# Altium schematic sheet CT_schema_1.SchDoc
size 785 x 593 mm
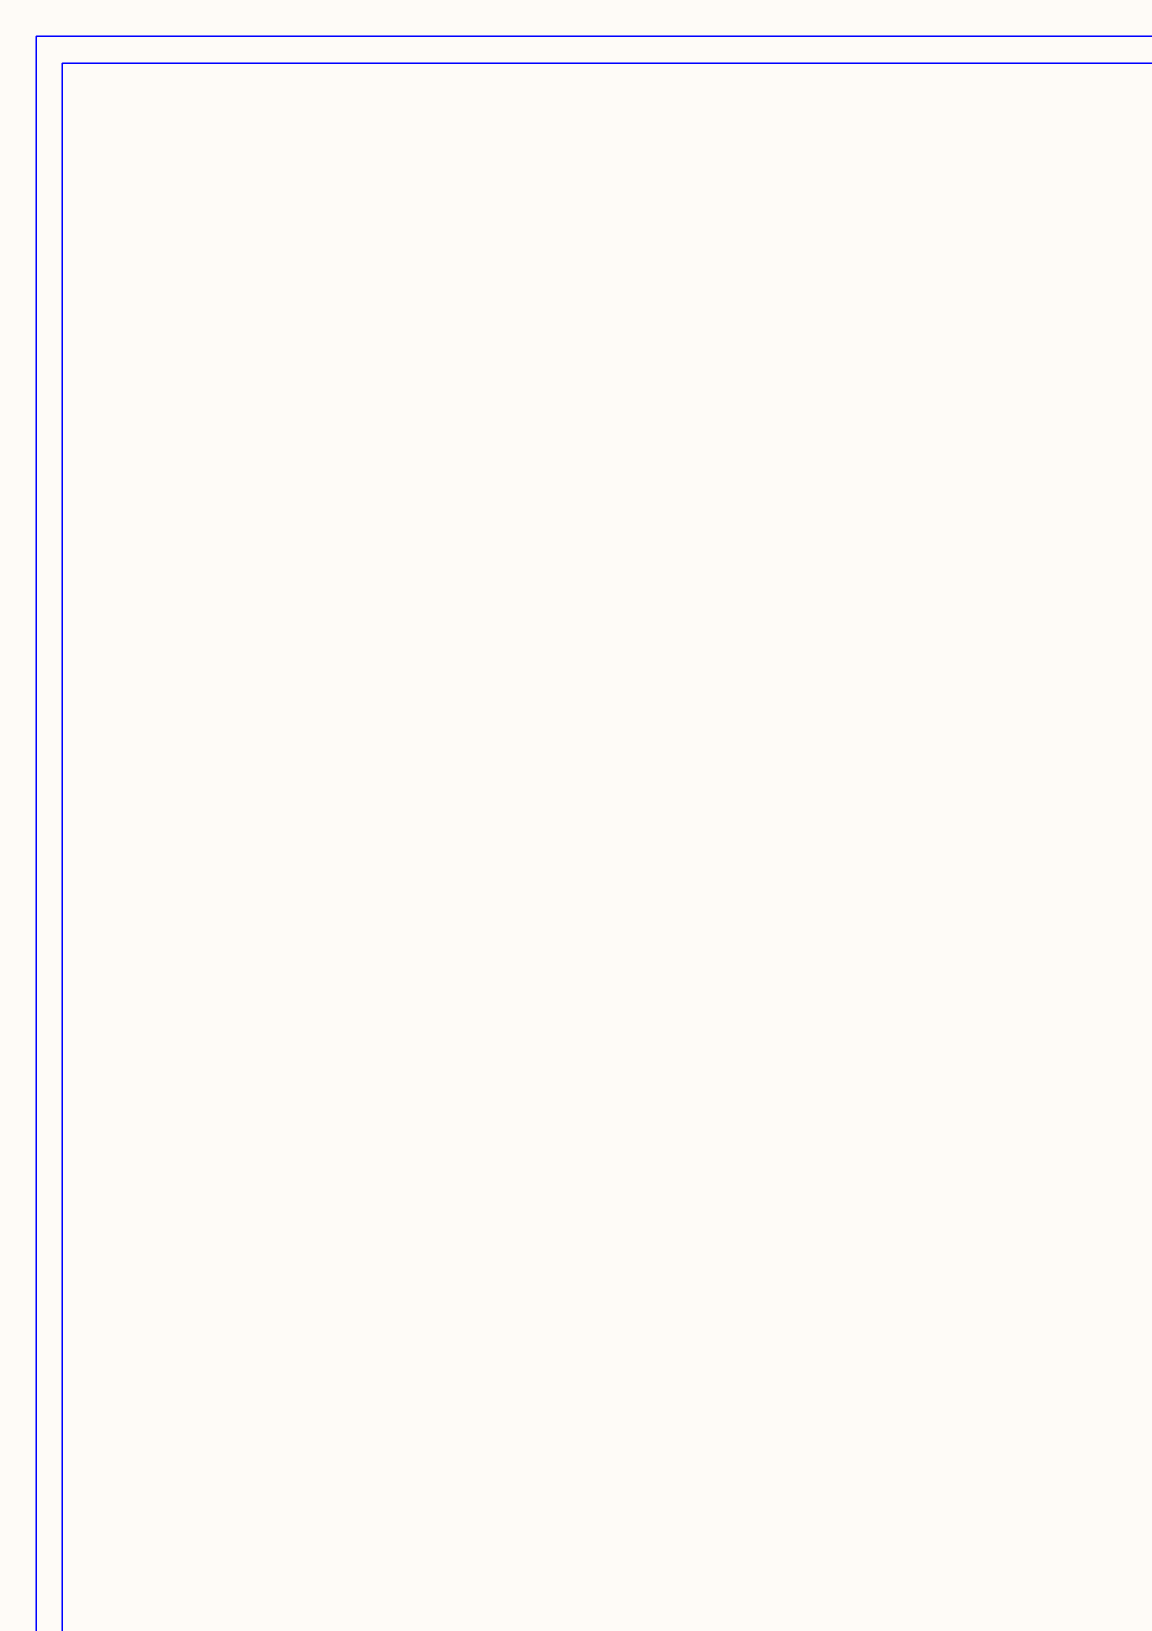
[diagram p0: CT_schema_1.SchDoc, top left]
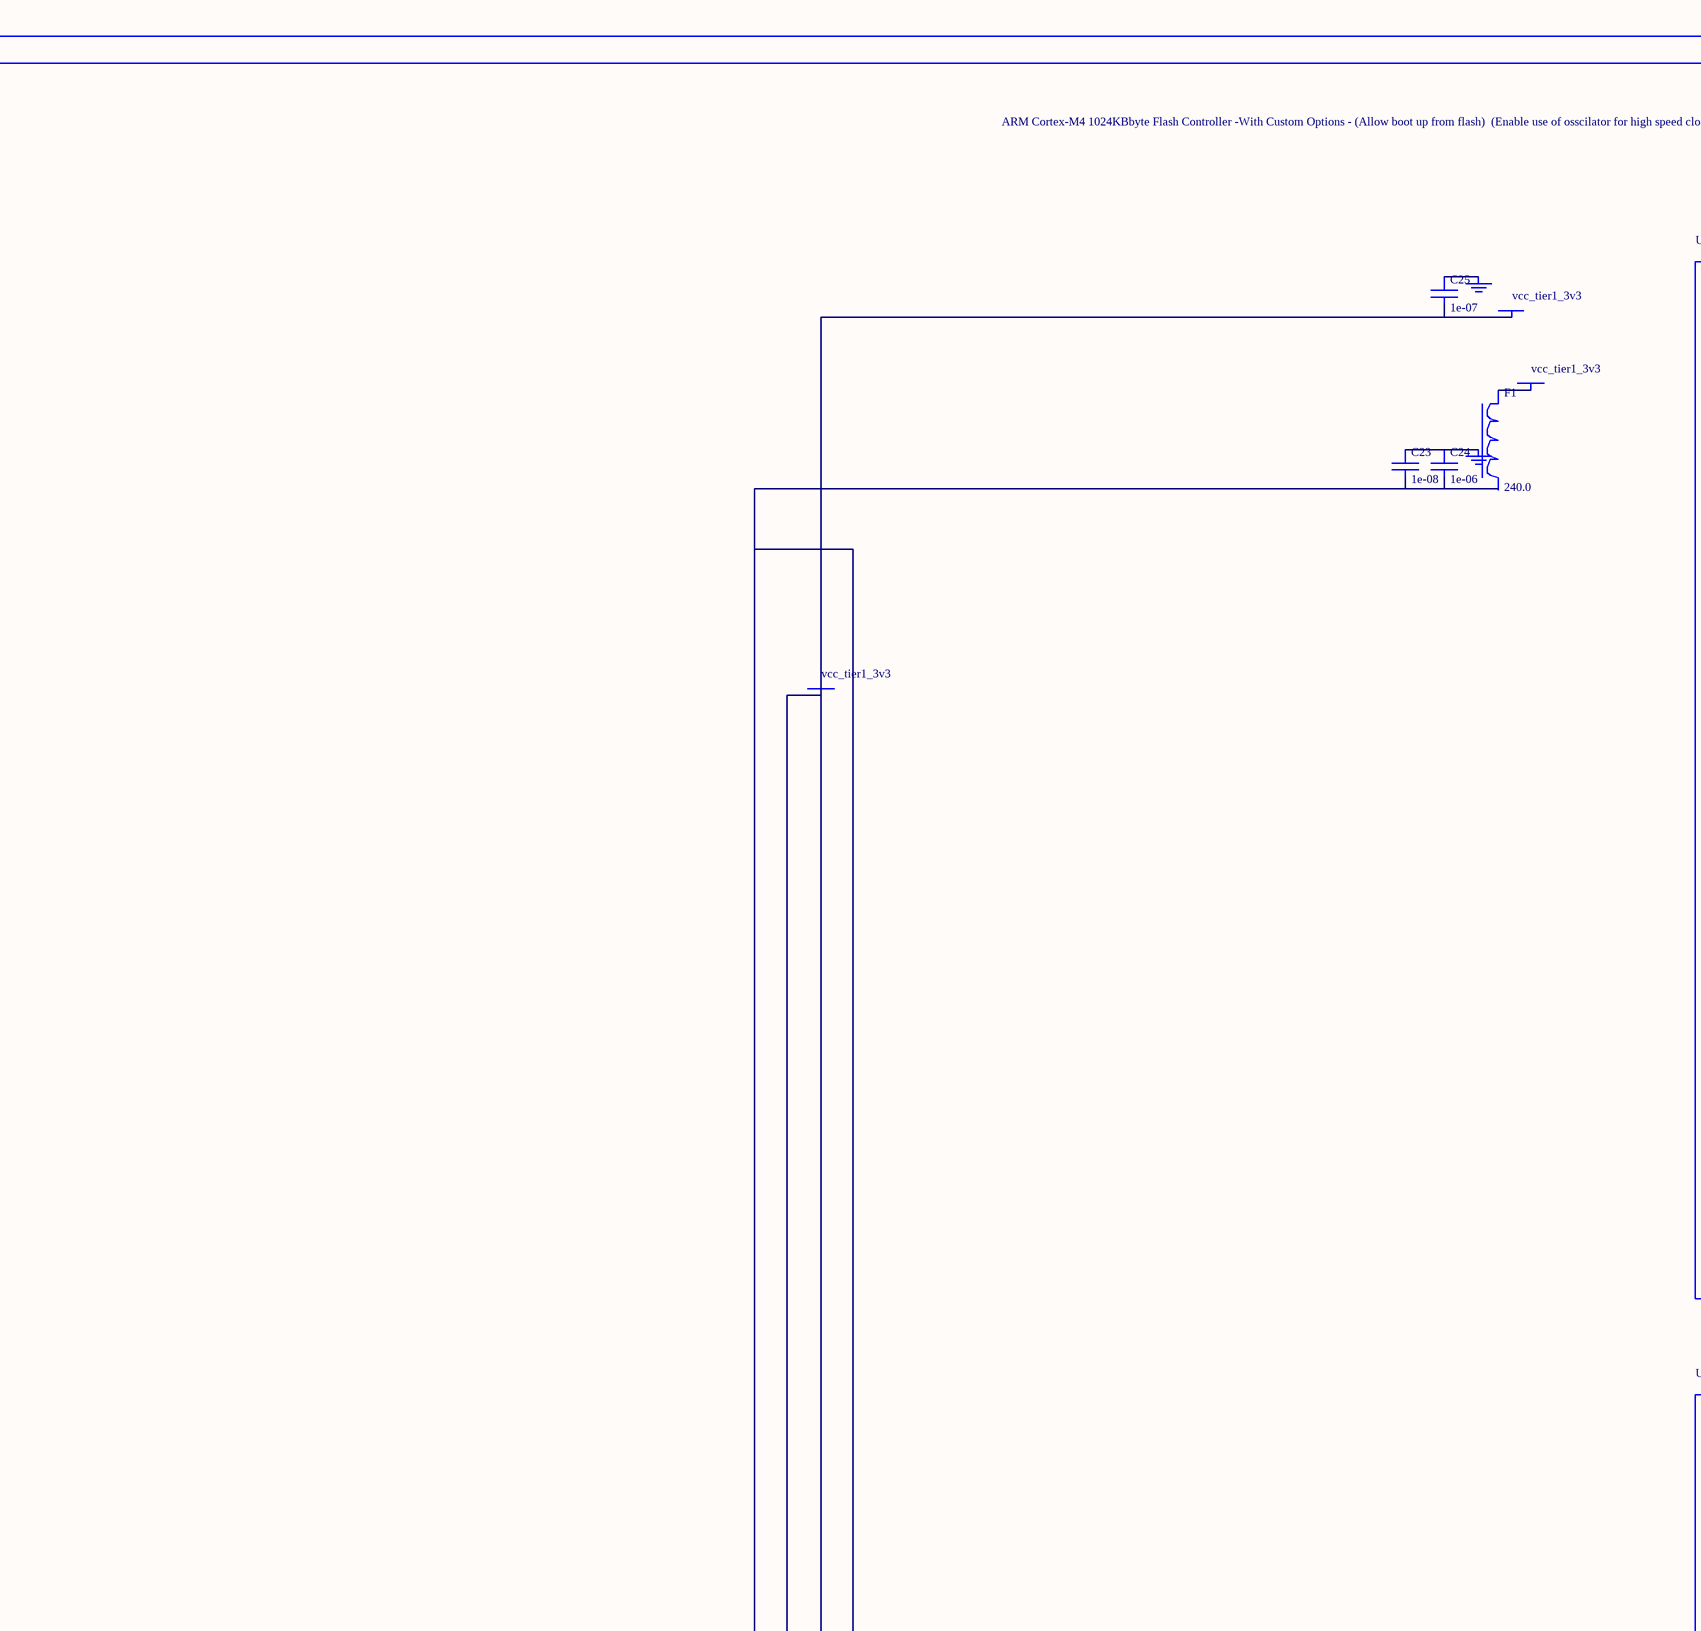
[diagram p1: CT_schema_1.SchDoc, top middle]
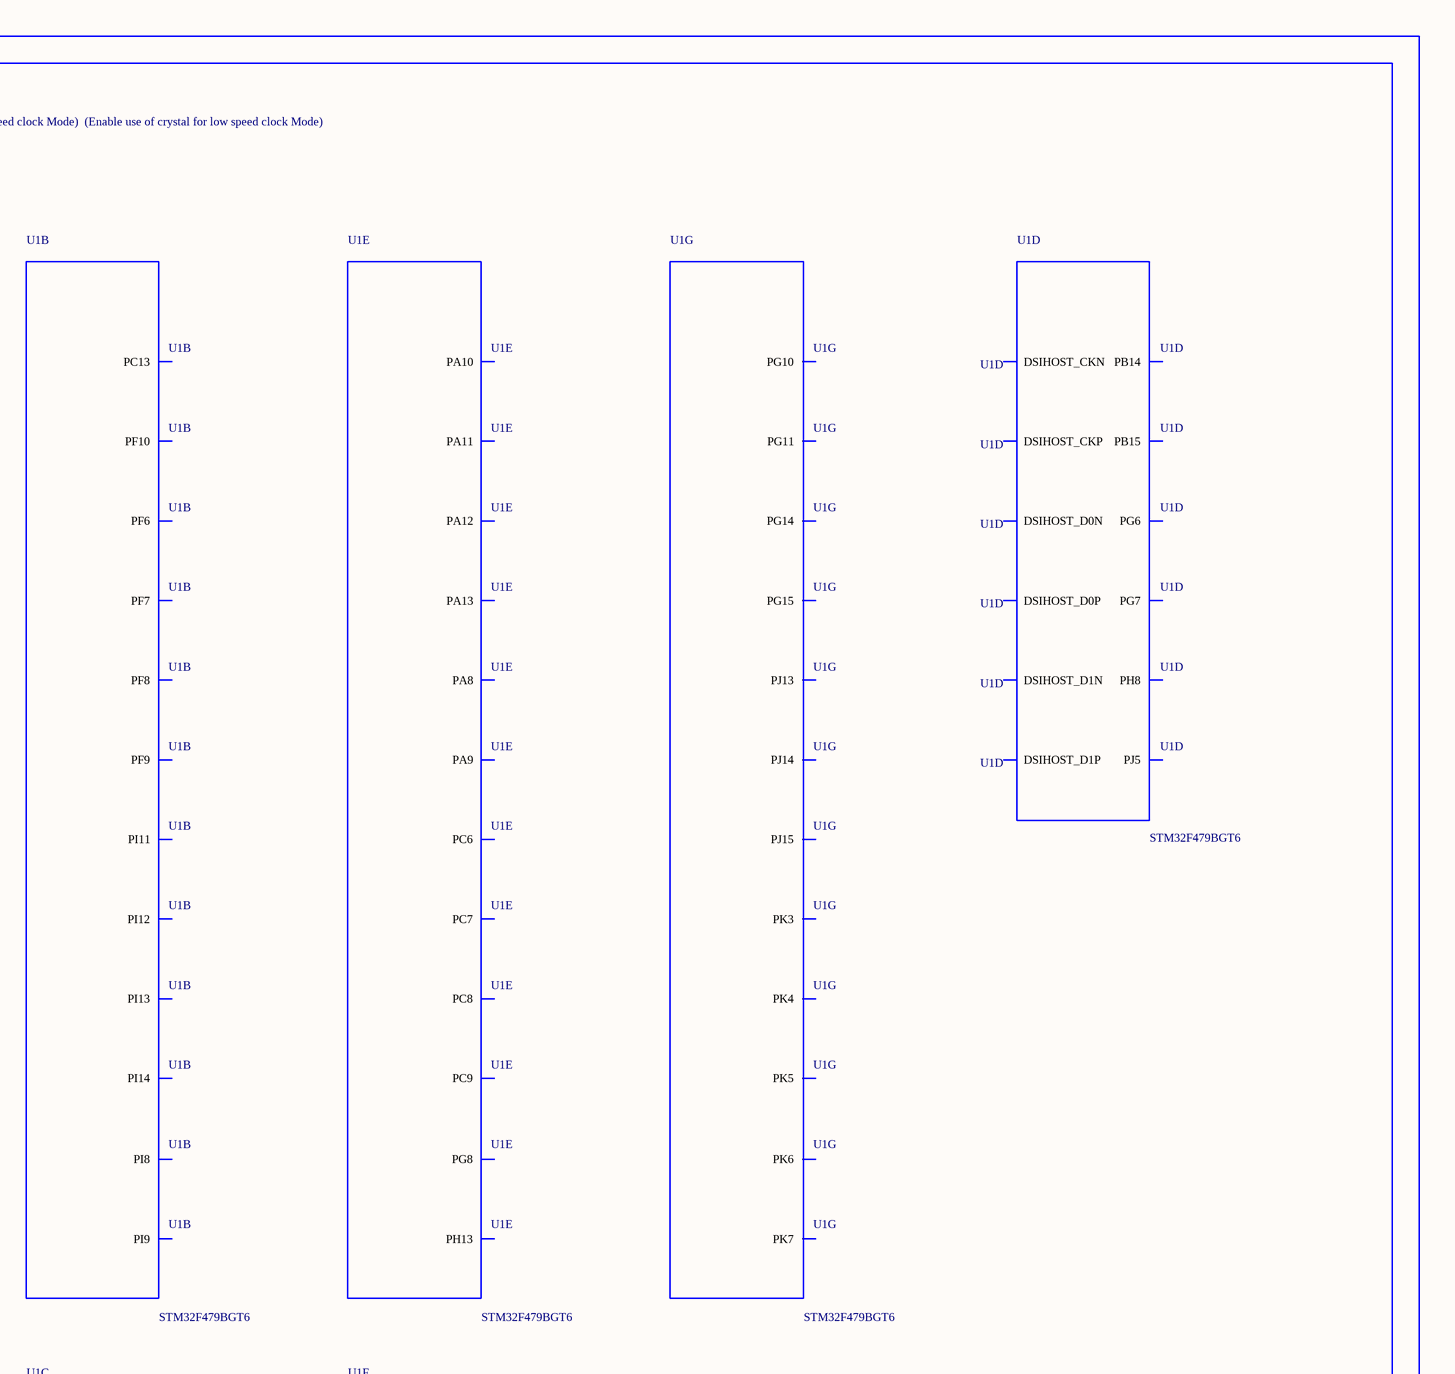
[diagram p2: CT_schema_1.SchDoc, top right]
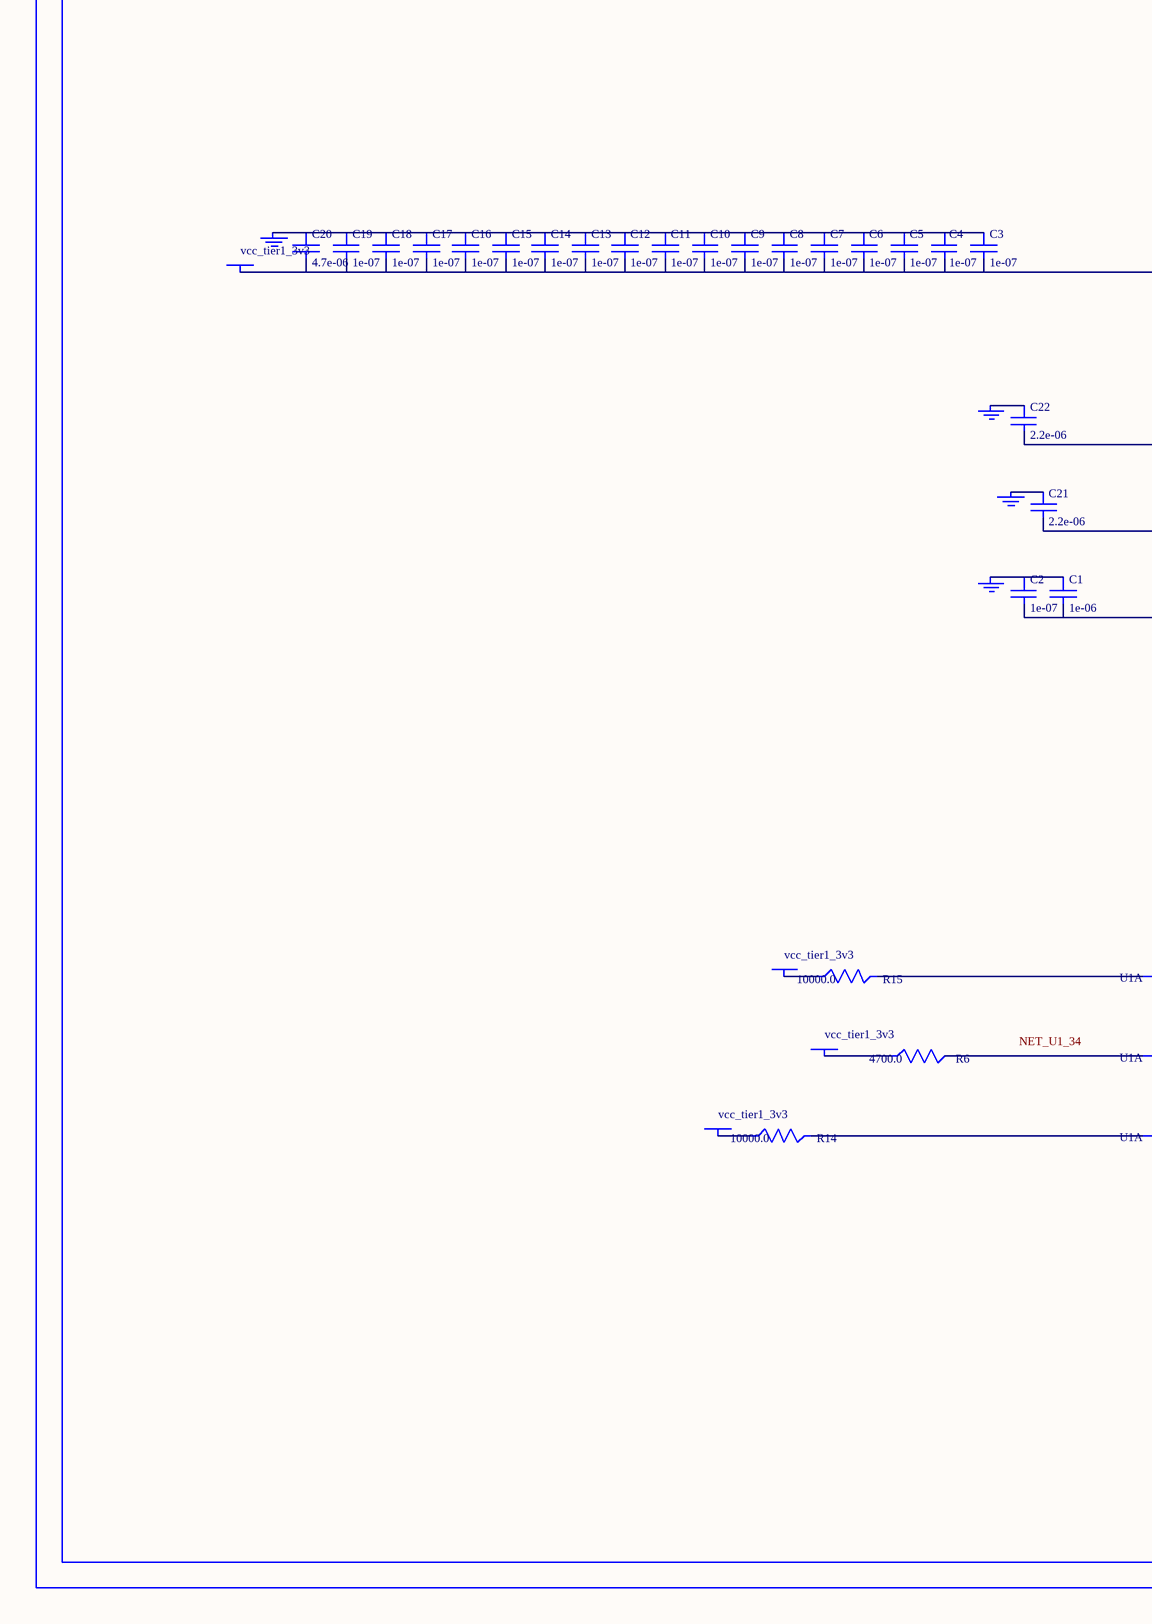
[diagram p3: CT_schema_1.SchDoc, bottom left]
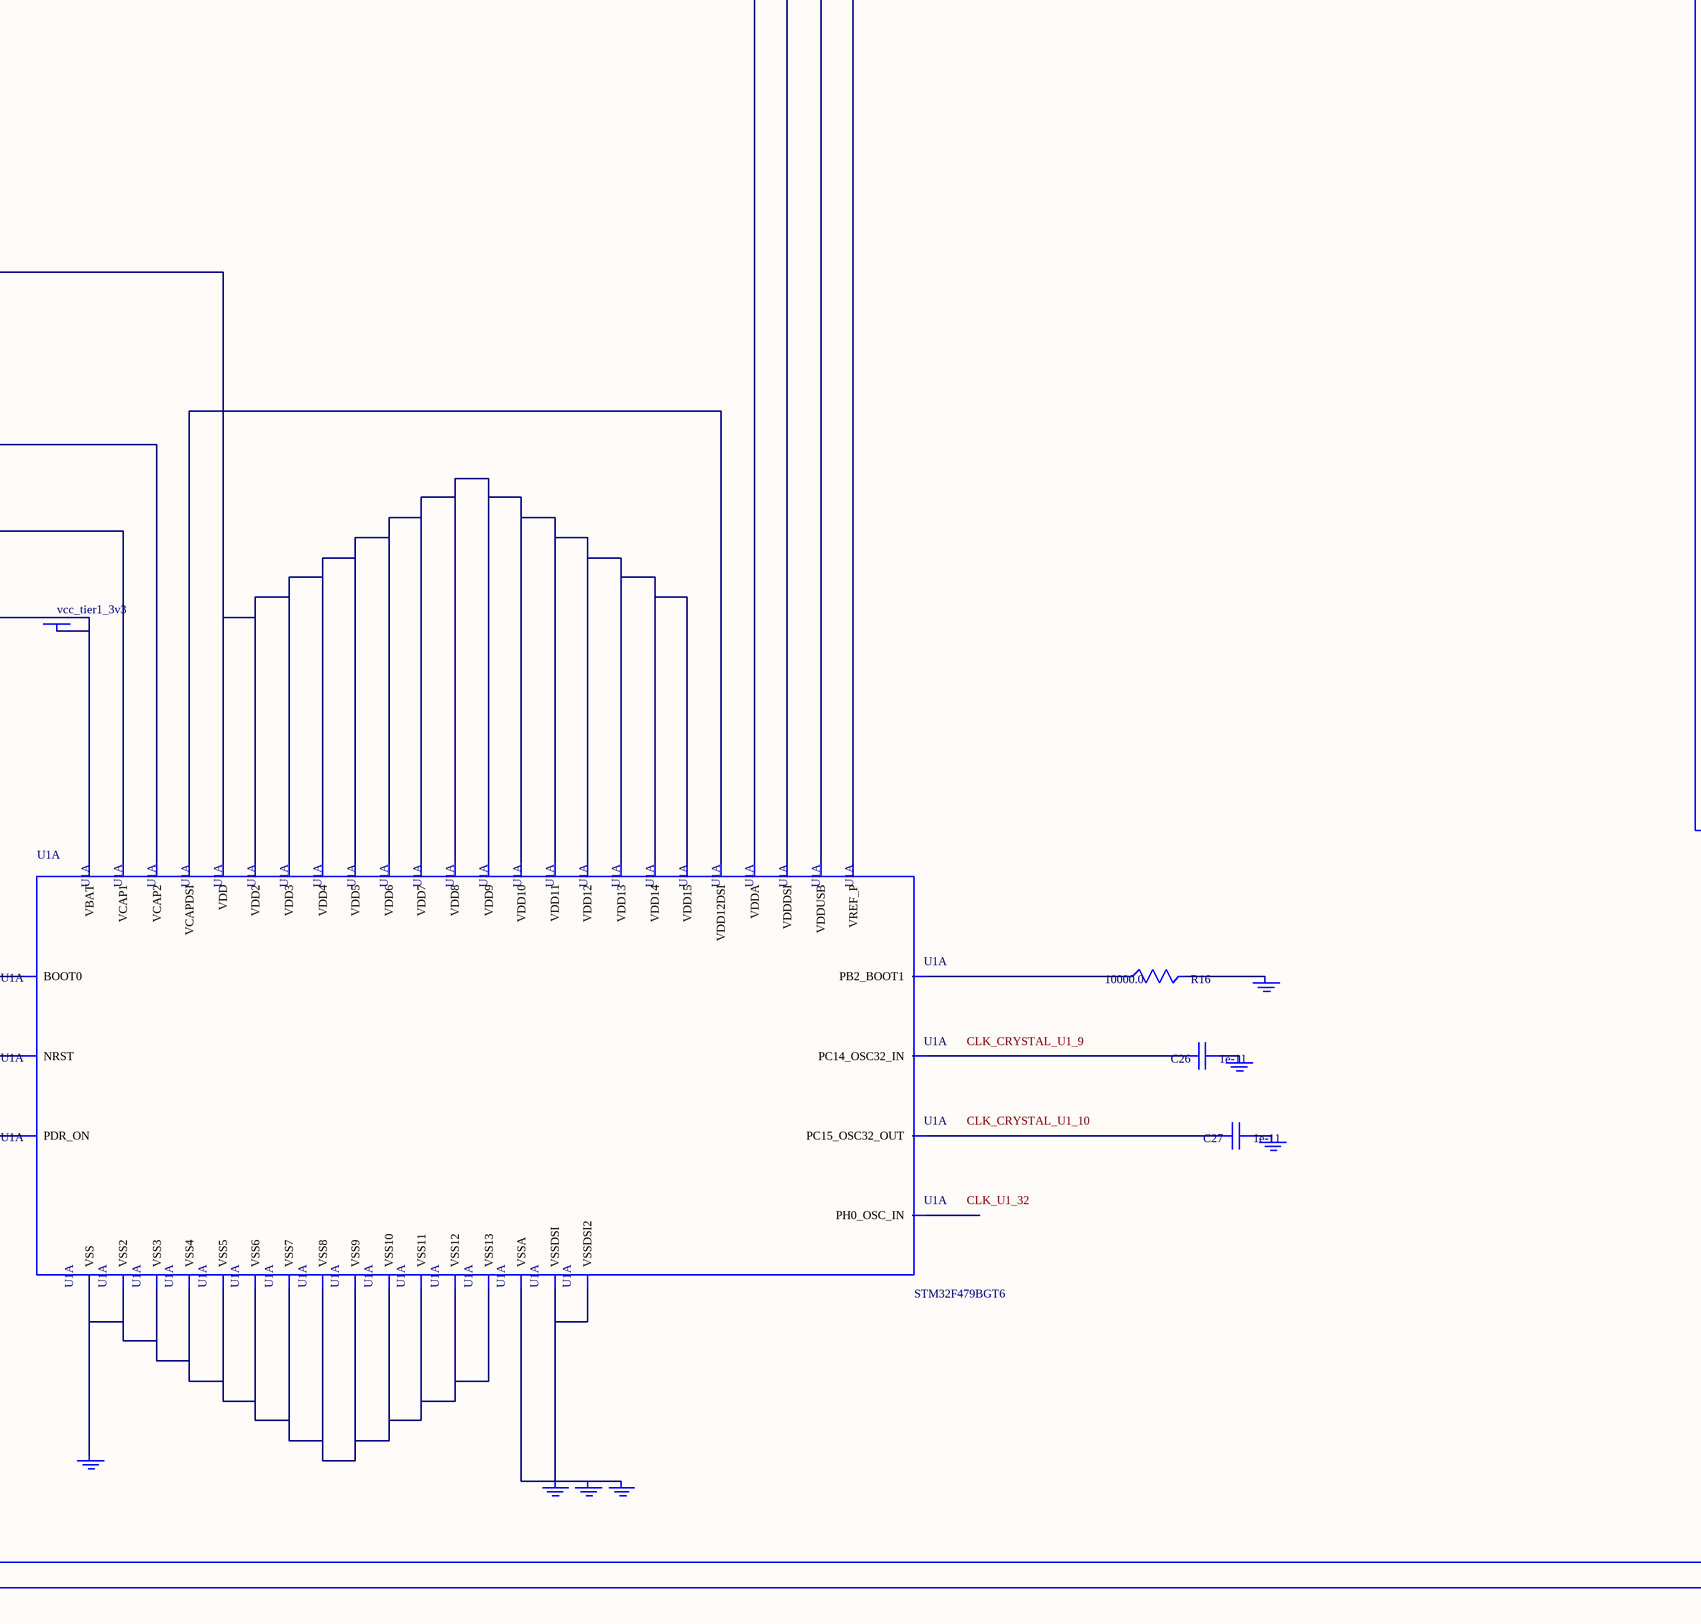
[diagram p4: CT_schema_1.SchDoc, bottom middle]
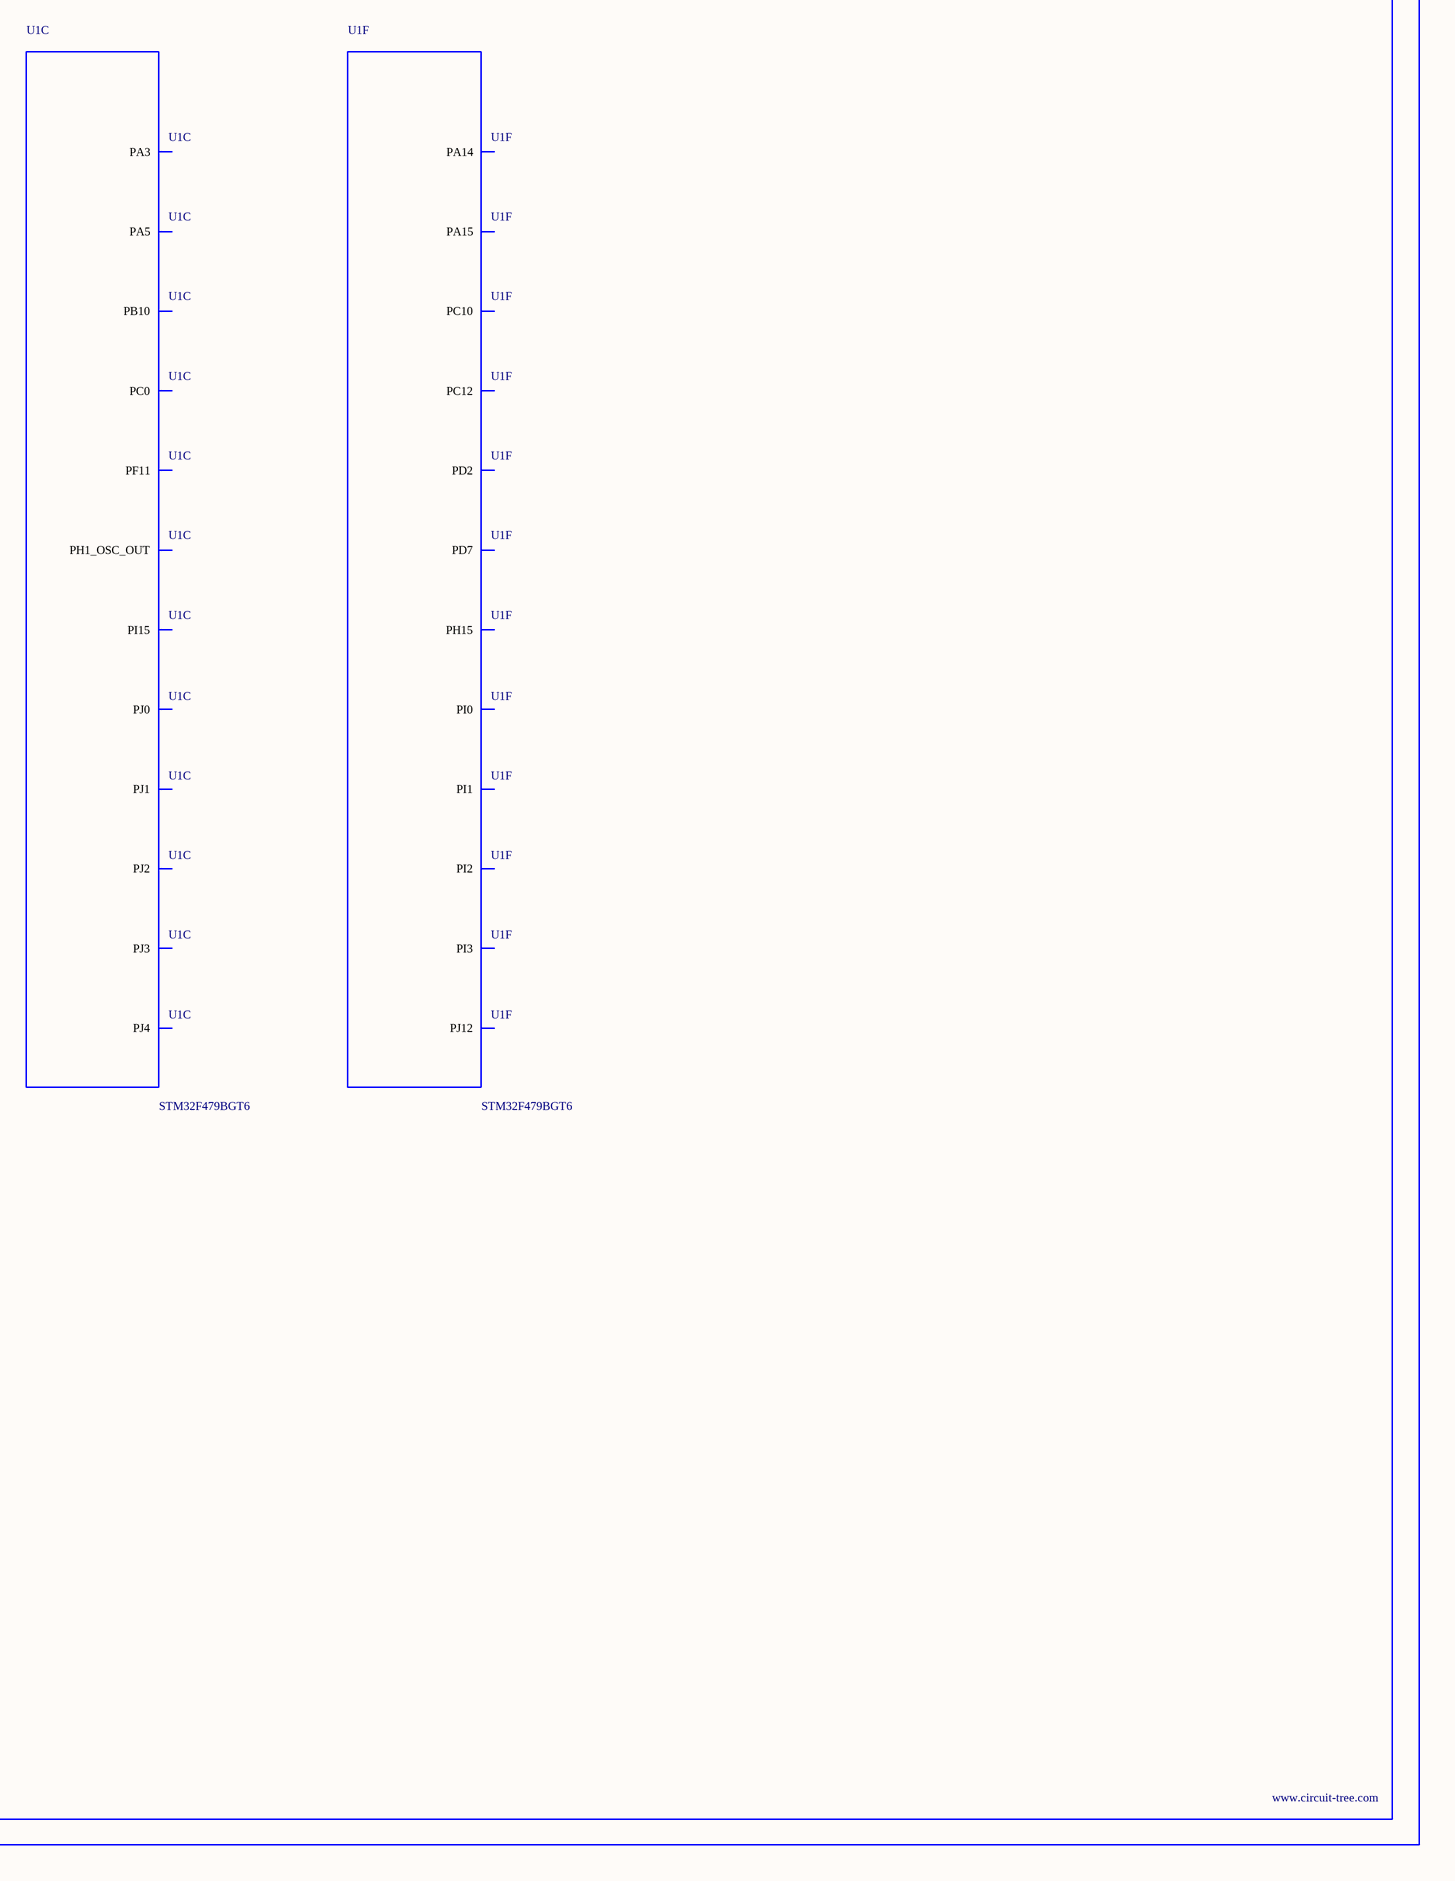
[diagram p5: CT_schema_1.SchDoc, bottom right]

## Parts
BORDER0  (no value)
C1  1e-06  [C0603]
C2  1e-07  [C0603]
C3  1e-07  [C0603]
C4  1e-07  [C0603]
C5  1e-07  [C0603]
C6  1e-07  [C0603]
C7  1e-07  [C0603]
C8  1e-07  [C0603]
C9  1e-07  [C0603]
C10  1e-07  [C0603]
C11  1e-07  [C0603]
C12  1e-07  [C0603]
C13  1e-07  [C0603]
C14  1e-07  [C0603]
C15  1e-07  [C0603]
C16  1e-07  [C0603]
C17  1e-07  [C0603]
C18  1e-07  [C0603]
C19  1e-07  [C0603]
C20  4.7e-06  [C0603]
C21  2.2e-06  [C0603]
C22  2.2e-06  [C0603]
C23  1e-08  [C0603]
C24  1e-06  [C0603]
C25  1e-07  [C0603]
C26  1e-11  [C0402]
C27  1e-11  [C0402]
F1  240.0  [L0603]
GND_INSTANCE_0_0  (no value)
GND_INSTANCE_0_1  (no value)
GND_INSTANCE_0_2  (no value)
GND_INSTANCE_0_3  (no value)
GND_INSTANCE_0_4  (no value)
GND_INSTANCE_0_5  (no value)
GND_INSTANCE_0_6  (no value)
GND_INSTANCE_0_7  (no value)
GND_INSTANCE_0_8  (no value)
GND_INSTANCE_0_9  (no value)
GND_INSTANCE_0_10  (no value)
GND_INSTANCE_0_11  (no value)
GND_INSTANCE_0_12  (no value)
POWER_INSTANCE_0_0  vcc_tier1_3v3
POWER_INSTANCE_0_1  vcc_tier1_3v3
POWER_INSTANCE_0_2  vcc_tier1_3v3
POWER_INSTANCE_0_3  vcc_tier1_3v3
POWER_INSTANCE_0_4  vcc_tier1_3v3
POWER_INSTANCE_0_5  vcc_tier1_3v3
POWER_INSTANCE_0_6  vcc_tier1_3v3
POWER_INSTANCE_0_7  vcc_tier1_3v3
R6  4700.0  [R0603]
R14  10000.0  [R0603]
R15  10000.0  [R0603]
R16  10000.0  [R0603]
U1  STM32F479BGT6  [LQFP208]  (parts A,B,C,D,E,F,G of 16)

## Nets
NetC1_1: C1.1 C2.1 GND_INSTANCE_0_0.0(GND)
NetC1_2: C1.2 C2.2 POWER_INSTANCE_0_0.0(PWR) U1.6(VBAT)
NetC3_1: C3.1 C4.1 C5.1 C6.1 C7.1 C8.1 C9.1 C10.1 C11.1 C12.1 C13.1 C14.1 C15.1 C16.1 C17.1 C18.1 C19.1 C20.1 GND_INSTANCE_0_3.0(GND)
NetC3_2: C3.2 C4.2 C5.2 C6.2 C7.2 C8.2 C9.2 C10.2 C11.2 C12.2 C13.2 C14.2 C15.2 C16.2 C17.2 C18.2 C19.2 C20.2 POWER_INSTANCE_0_1.0(PWR) U1.15(VDD) U1.26(VDD2) U1.39(VDD3) U1.52(VDD4) U1.59(VDD5) U1.73(VDD6) U1.83(VDD7) U1.94(VDD8) U1.103(VDD9) U1.115(VDD10) U1.150(VDD11) U1.158(VDD12) U1.171(VDD13) U1.185(VDD14) U1.204(VDD15)
NetC21_1: C21.1 GND_INSTANCE_0_7.0(GND)
NetC21_2: C21.2 U1.92(VCAP1)
NetC22_1: C22.1 GND_INSTANCE_0_11.0(GND)
NetC22_2: C22.2 U1.148(VCAP2)
NetC23_1: C23.1 C24.1 GND_INSTANCE_0_5.0(GND)
NetC23_2: C23.2 C24.2 U1.41(VREF_P) U1.42(VDDA)
NetC25_1: C25.1 GND_INSTANCE_0_10.0(GND)
NetC25_2: C25.2 POWER_INSTANCE_0_3.0(PWR) POWER_INSTANCE_0_4.0(PWR) U1.118(VDDDSI) U1.137(VDDUSB)
NetC26_1: C26.1 GND_INSTANCE_0_1.0(GND)
NetC26_2: C26.2 U1.9(PC14_OSC32_IN)
NetC27_1: C27.1 GND_INSTANCE_0_2.0(GND)
NetC27_2: C27.2 U1.10(PC15_OSC32_OUT)
NetF1_1: F1.1 POWER_INSTANCE_0_2.0(PWR)
NetGND_INSTANCE_0_4_0: GND_INSTANCE_0_4.0(GND) GND_INSTANCE_0_8.0(GND) GND_INSTANCE_0_9.0(GND) U1.40(VSSA) U1.122(VSSDSI) U1.128(VSSDSI2)
NetGND_INSTANCE_0_6_0: GND_INSTANCE_0_6.0(GND) R16.2
NetGND_INSTANCE_0_12_0: GND_INSTANCE_0_12.0(GND) U1.14(VSS) U1.25(VSS2) U1.51(VSS3) U1.60(VSS4) U1.72(VSS5) U1.82(VSS6) U1.93(VSS7) U1.114(VSS8) U1.136(VSS9) U1.149(VSS10) U1.170(VSS11) U1.184(VSS12) U1.202(VSS13)
NetPOWER_INSTANCE_0_5_0: POWER_INSTANCE_0_5.0(PWR) R15.1
NetPOWER_INSTANCE_0_6_0: POWER_INSTANCE_0_6.0(PWR) R14.1
NetPOWER_INSTANCE_0_7_0: POWER_INSTANCE_0_7.0(PWR) R6.1
NetR6_2: R6.2 U1.34(NRST)
NetR14_2: R14.2 U1.203(PDR_ON)
NetR15_2: R15.2 U1.197(BOOT0)
NetR16_1: R16.1 U1.63(PB2_BOOT1)
NetU1_119: U1.119(VCAPDSI) U1.125(VDD12DSI)

Not connected (* = marked no-connect by the designer): F1 2; U1 7(PI8) 8(PC13) 11(PI9) 13(PI11) 19(PI12) 20(PI13) 21(PI14) 27(PF6) 28(PF7) 29(PF8) 30(PF9) 31(PF10) 32(PH0_OSC_IN) 33(PH1_OSC_OUT) 35(PC0) 50(PA3) 54(PA5) 64(PI15) 65(PJ0) 66(PJ1) 67(PJ2) 68(PJ3) 69(PJ4) 70(PF11) 90(PB10) 95(PJ5) 98(PH8) 106(PB14) 107(PB15) 120(DSIHOST_D0P) 121(DSIHOST_D0N) 123(DSIHOST_CKP) 124(DSIHOST_CKN) 126(DSIHOST_D1P) 127(DSIHOST_D1N) 133(PG6) 134(PG7) 135(PG8) 138(PC6) 139(PC7) 140(PC8) 141(PC9) 142(PA8) 143(PA9) 144(PA10) 145(PA11) 146(PA12) 147(PA13) 151(PH13) 153(PH15) 154(PI0) 155(PI1) 156(PI2) 157(PI3) 159(PA14) 160(PA15) 161(PC10) 163(PC12) 166(PD2) 173(PD7) 174(PJ12) 175(PJ13) 176(PJ14) 177(PJ15) 179(PG10) 180(PG11) 183(PG14) 186(PK3) 187(PK4) 188(PK5) 189(PK6) 190(PK7) 191(PG15)

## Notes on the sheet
- Labels drawn without touching a wire or pin: CLK_CRYSTAL_U1_9, CLK_CRYSTAL_U1_10, CLK_U1_32, NET_U1_34

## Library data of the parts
BORDER0 = BORDER_PAGE0
C1 C24 = C0603C105K3RACTU
C2-C19 C25 = 06035C104K4Z2A
C20 = GRM188R6YA475KE15D
C21 C22 = C0603C225K8RACTU
C23 = 06035C103K4Z2A
C26 C27 = C0402C100K3GACTU
F1 = Z0603C241ASMST
GND_INSTANCE_0_0-GND_INSTANCE_0_12 = GND
POWER_INSTANCE_0_0-POWER_INSTANCE_0_7 = PWR
R6 = RC0603JR-074K7L
R14-R16 = RC0603JR-0710KL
